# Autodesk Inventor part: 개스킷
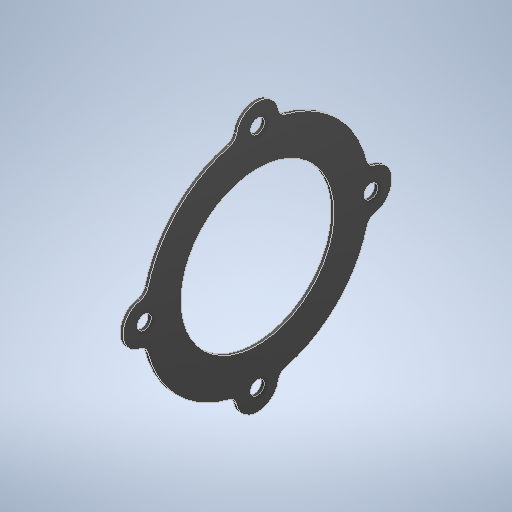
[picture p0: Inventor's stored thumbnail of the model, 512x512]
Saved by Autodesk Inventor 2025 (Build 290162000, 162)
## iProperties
Created: 2024-08
Part Number: 개스킷
Material: 황동, 연질 노란색
Document SubType Name: Modeling
Designer: deana
Density: 8.47 g/cm^3
Appearance: 기본값
Author: jhkim
Sending System: Autodesk Inventor 2025
Preprocessor: ST-DEVELOPER v20
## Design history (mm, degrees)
feature "솔리드2"
node "솔리드1"
